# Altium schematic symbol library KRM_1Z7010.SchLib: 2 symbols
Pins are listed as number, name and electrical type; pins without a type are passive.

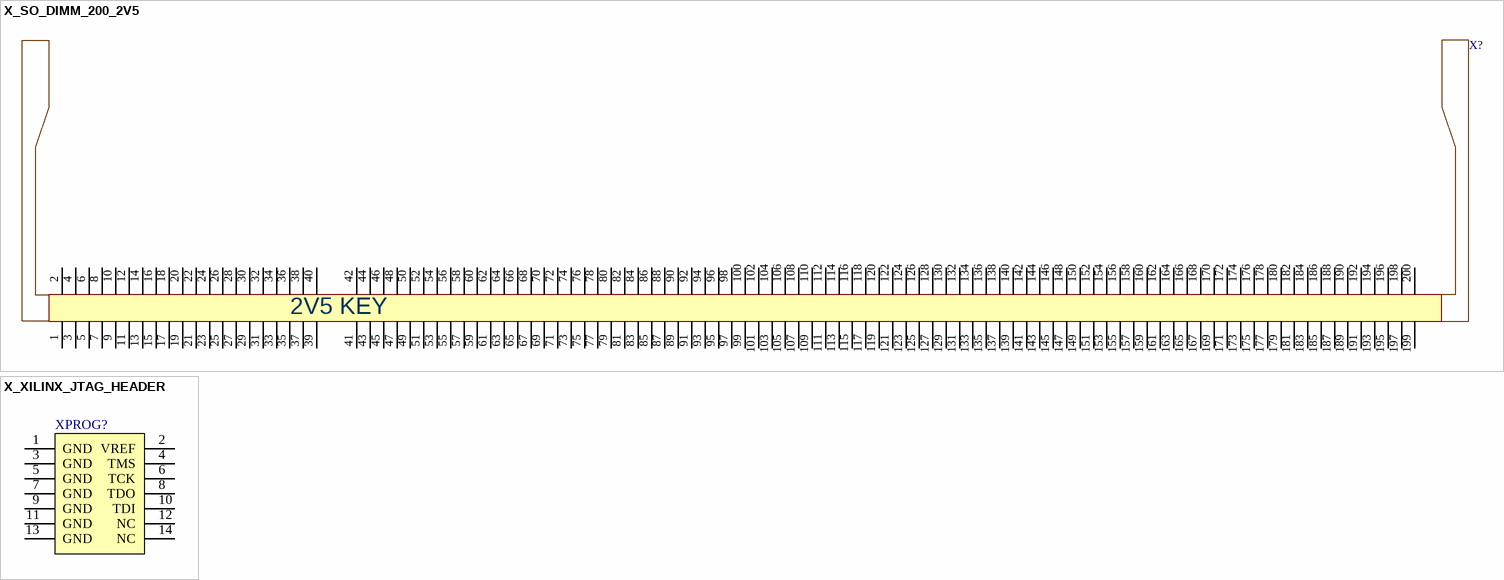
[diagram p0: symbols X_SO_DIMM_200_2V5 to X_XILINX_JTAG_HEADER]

## X_SO_DIMM_200_2V5
designator X?  (value not drawn)
200PIN SO DIMM DDR1 SOCKET 5.2MM R/A
footprint DDR1_SODIMM
pins: 1, 2, 3, 4, 5, 6, 7, 8, 9, 10, 11, 12, 13, 14, 15, 16, 17, 18, 19, 20, 21, 22, 23, 24, 25, 26, 27, 28, 29, 30, 31, 32, 33, 34, 35, 36, 37, 38, 39, 40, 41, 42, 43, 44, 45, 46, 47, 48, 49, 50, 51, 52, 53, 54, 55, 56, 57, 58, 59, 60, 61, 62, 63, 64, 65, 66, 67, 68, 69, 70, 71, 72, 73, 74, 75, 76, 77, 78, 79, 80, 81, 82, 83, 84, 85, 86, 87, 88, 89, 90, 91, 92, 93, 94, 95, 96, 97, 98, 99, 100, 101, 102, 103, 104, 105, 106, 107, 108, 109, 110, 111, 112, 113, 114, 115, 116, 117, 118, 119, 120, 121, 122, 123, 124, 125, 126, 127, 128, 129, 130, 131, 132, 133, 134, 135, 136, 137, 138, 139, 140, 141, 142, 143, 144, 145, 146, 147, 148, 149, 150, 151, 152, 153, 154, 155, 156, 157, 158, 159, 160, 161, 162, 163, 164, 165, 166, 167, 168, 169, 170, 171, 172, 173, 174, 175, 176, 177, 178, 179, 180, 181, 182, 183, 184, 185, 186, 187, 188, 189, 190, 191, 192, 193, 194, 195, 196, 197, 198, 199, 200

## X_XILINX_JTAG_HEADER
designator XPROG?  (value not drawn)
14PIN 2mm VERT SHROUDED LOCATOR
footprint 14 PIN 2MM SMD
footprint X_2X7_2_SMD_M_WO_BG
pins: 1 GND, 2 VREF, 3 GND, 4 TMS, 5 GND, 6 TCK, 7 GND, 8 TDO, 9 GND, 10 TDI, 11 GND, 12 NC, 13 GND, 14 NC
